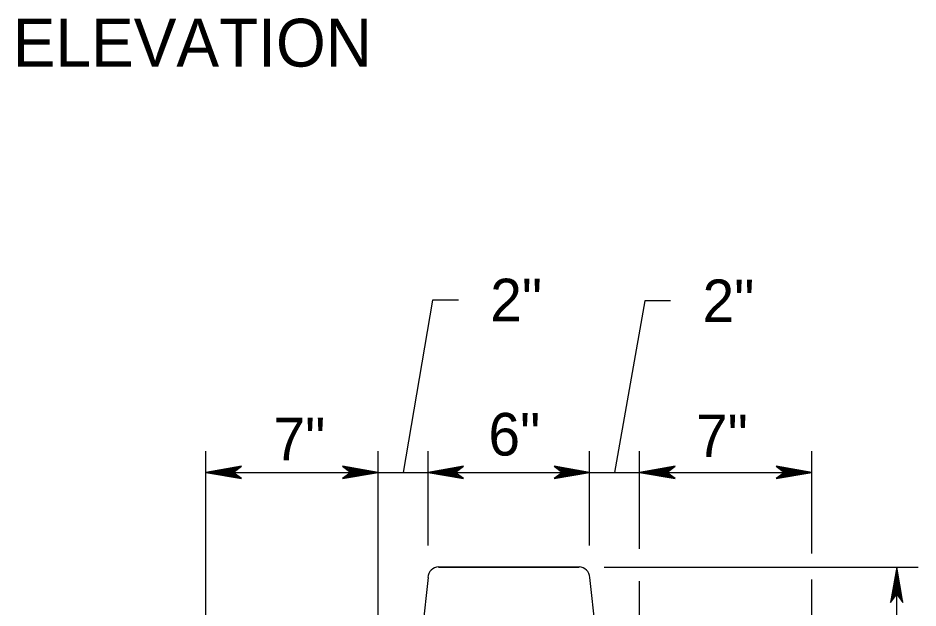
# Model space of a CAD drawing. Extents: x 499866 to 500993, y 499985 to 500645.
# Drawn here: x 500327.9 to 500412.5, y 500404.9 to 500460.3 of the extents above; entities that cross this region are included whole.
import ezdxf

# ---------------------------------------------------------------- set-up
doc = ezdxf.new("R2010")
doc.units = 0
doc.layers.add('24', color=7, linetype='Continuous')
doc.layers.add('5', color=7, linetype='Continuous')

msp = doc.modelspace()

# ---------------------------------------------------------------- linework, layer by layer
at = {"layer": '24'}
for points in [[(500345.582, 500417.598), (500348.932, 500417.006), (500348.132, 500417.598), (500348.915, 500418.181), (500345.582, 500417.598), (500345.804, 500417.604), (500348.838, 500417.05), (500348.069, 500417.605), (500348.78, 500418.135), (500345.925, 500417.614), (500346.036, 500417.598), (500348.635, 500417.136), (500348.052, 500417.605), (500348.651, 500418.059), (500346.087, 500417.597), (500346.198, 500417.614), (500348.47, 500417.204), (500348.028, 500417.597), (500348.479, 500418.006), (500346.522, 500417.615), (500346.711, 500417.614), (500348.302, 500417.289), (500347.992, 500417.588), (500348.325, 500417.921), (500346.745, 500417.598), (500346.924, 500417.587), (500348.119, 500417.383), (500347.889, 500417.615), (500348.139, 500417.844), (500347.088, 500417.598), (500347.257, 500417.581), (500347.975, 500417.444), (500347.857, 500417.605), (500348.052, 500417.784), (500347.344, 500417.597), (500347.813, 500417.486), (500347.745, 500417.614), (500347.95, 500417.743), (500347.462, 500417.615), (500347.769, 500417.538), (500347.64, 500417.639), (500347.788, 500417.699), (500347.641, 500417.605), (500347.718, 500417.588)], [(500361.763, 500417.598), (500358.413, 500418.19), (500359.214, 500417.598), (500358.43, 500417.015), (500361.763, 500417.598), (500361.541, 500417.592), (500358.507, 500418.146), (500359.276, 500417.591), (500358.566, 500417.061), (500361.421, 500417.581), (500361.309, 500417.598), (500358.71, 500418.06), (500359.293, 500417.591), (500358.694, 500417.136), (500361.258, 500417.598), (500361.147, 500417.581), (500358.875, 500417.991), (500359.317, 500417.598), (500358.866, 500417.189), (500360.823, 500417.581), (500360.634, 500417.581), (500359.044, 500417.907), (500359.353, 500417.607), (500359.02, 500417.274), (500360.6, 500417.598), (500360.422, 500417.608), (500359.226, 500417.813), (500359.456, 500417.581), (500359.206, 500417.352), (500360.257, 500417.598), (500360.089, 500417.615), (500359.37, 500417.752), (500359.489, 500417.591), (500359.293, 500417.412), (500360.001, 500417.598), (500359.532, 500417.709), (500359.6, 500417.581), (500359.395, 500417.453), (500359.883, 500417.581), (500359.576, 500417.658), (500359.705, 500417.557), (500359.557, 500417.496), (500359.704, 500417.591), (500359.627, 500417.607)], [(500366.46, 500417.598), (500369.81, 500417.006), (500369.01, 500417.598), (500369.793, 500418.181), (500366.46, 500417.598), (500366.683, 500417.604), (500369.717, 500417.05), (500368.948, 500417.605), (500369.658, 500418.135), (500366.803, 500417.614), (500366.914, 500417.598), (500369.513, 500417.136), (500368.93, 500417.605), (500369.53, 500418.059), (500366.966, 500417.597), (500367.077, 500417.614), (500369.348, 500417.204), (500368.906, 500417.597), (500369.358, 500418.006), (500367.4, 500417.615), (500367.589, 500417.614), (500369.18, 500417.289), (500368.87, 500417.588), (500369.204, 500417.921), (500367.623, 500417.598), (500367.802, 500417.587), (500368.998, 500417.383), (500368.768, 500417.615), (500369.017, 500417.844), (500367.966, 500417.598), (500368.135, 500417.581), (500368.853, 500417.444), (500368.735, 500417.605), (500368.93, 500417.784), (500368.222, 500417.597), (500368.691, 500417.486), (500368.623, 500417.614), (500368.829, 500417.743), (500368.34, 500417.615), (500368.648, 500417.538), (500368.519, 500417.639), (500368.667, 500417.699), (500368.52, 500417.605), (500368.596, 500417.588)], [(500381.66, 500417.598), (500378.31, 500418.19), (500379.111, 500417.598), (500378.328, 500417.015), (500381.66, 500417.598), (500381.438, 500417.592), (500378.404, 500418.146), (500379.173, 500417.591), (500378.463, 500417.061), (500381.318, 500417.581), (500381.206, 500417.598), (500378.608, 500418.06), (500379.191, 500417.591), (500378.591, 500417.136), (500381.155, 500417.598), (500381.044, 500417.581), (500378.772, 500417.991), (500379.214, 500417.598), (500378.763, 500417.189), (500380.72, 500417.581), (500380.531, 500417.581), (500378.941, 500417.907), (500379.25, 500417.607), (500378.917, 500417.274), (500380.498, 500417.598), (500380.319, 500417.608), (500379.123, 500417.813), (500379.353, 500417.581), (500379.104, 500417.352), (500380.155, 500417.598), (500379.986, 500417.615), (500379.267, 500417.752), (500379.386, 500417.591), (500379.19, 500417.412), (500379.898, 500417.598), (500379.43, 500417.709), (500379.498, 500417.581), (500379.292, 500417.453), (500379.781, 500417.581), (500379.473, 500417.658), (500379.602, 500417.557), (500379.454, 500417.496), (500379.601, 500417.591), (500379.524, 500417.607)], [(500386.357, 500417.598), (500389.707, 500417.006), (500388.907, 500417.598), (500389.69, 500418.181), (500386.357, 500417.598), (500386.58, 500417.604), (500389.614, 500417.05), (500388.844, 500417.605), (500389.555, 500418.135), (500386.7, 500417.614), (500386.811, 500417.598), (500389.41, 500417.136), (500388.827, 500417.605), (500389.427, 500418.059), (500386.863, 500417.597), (500386.974, 500417.614), (500389.245, 500417.204), (500388.803, 500417.597), (500389.255, 500418.006), (500387.297, 500417.615), (500387.486, 500417.614), (500389.077, 500417.289), (500388.767, 500417.588), (500389.101, 500417.921), (500387.52, 500417.598), (500387.699, 500417.587), (500388.895, 500417.383), (500388.665, 500417.615), (500388.914, 500417.844), (500387.863, 500417.598), (500388.032, 500417.581), (500388.75, 500417.444), (500388.632, 500417.605), (500388.827, 500417.784), (500388.119, 500417.597), (500388.588, 500417.486), (500388.52, 500417.614), (500388.726, 500417.743), (500388.237, 500417.615), (500388.545, 500417.538), (500388.416, 500417.639), (500388.564, 500417.699), (500388.417, 500417.605), (500388.493, 500417.588)], [(500402.539, 500417.598), (500399.189, 500418.19), (500399.989, 500417.598), (500399.206, 500417.015), (500402.539, 500417.598), (500402.316, 500417.592), (500399.282, 500418.146), (500400.052, 500417.591), (500399.341, 500417.061), (500402.196, 500417.581), (500402.085, 500417.598), (500399.486, 500418.06), (500400.069, 500417.591), (500399.469, 500417.136), (500402.033, 500417.598), (500401.922, 500417.581), (500399.651, 500417.991), (500400.093, 500417.598), (500399.641, 500417.189), (500401.599, 500417.581), (500401.41, 500417.581), (500399.819, 500417.907), (500400.129, 500417.607), (500399.795, 500417.274), (500401.376, 500417.598), (500401.197, 500417.608), (500400.001, 500417.813), (500400.231, 500417.581), (500399.982, 500417.352), (500401.033, 500417.598), (500400.864, 500417.615), (500400.146, 500417.752), (500400.264, 500417.591), (500400.069, 500417.412), (500400.777, 500417.598), (500400.308, 500417.709), (500400.376, 500417.581), (500400.17, 500417.453), (500400.659, 500417.581), (500400.351, 500417.658), (500400.48, 500417.557), (500400.332, 500417.496), (500400.479, 500417.591), (500400.403, 500417.607)], [(500410.532, 500408.703), (500409.94, 500405.353), (500410.532, 500406.153), (500411.115, 500405.37), (500410.532, 500408.703), (500410.538, 500408.48), (500409.984, 500405.447), (500410.54, 500406.216), (500411.07, 500405.505), (500410.549, 500408.36), (500410.532, 500408.249), (500410.071, 500405.65), (500410.539, 500406.233), (500410.994, 500405.634), (500410.532, 500408.198), (500410.549, 500408.086), (500410.139, 500405.815), (500410.532, 500406.257), (500410.941, 500405.805), (500410.55, 500407.763), (500410.549, 500407.574), (500410.223, 500405.983), (500410.523, 500406.293), (500410.856, 500405.959), (500410.532, 500407.54), (500410.522, 500407.361), (500410.317, 500406.165), (500410.55, 500406.395), (500410.779, 500406.146), (500410.532, 500407.197), (500410.515, 500407.028), (500410.378, 500406.31), (500410.54, 500406.428), (500410.719, 500406.233), (500410.532, 500406.941), (500410.421, 500406.472), (500410.549, 500406.54), (500410.677, 500406.334), (500410.55, 500406.823), (500410.472, 500406.515), (500410.573, 500406.644), (500410.634, 500406.496), (500410.54, 500406.643), (500410.523, 500406.567)]]:
    msp.add_lwpolyline(points, dxfattribs=at)
at = {"layer": '5'}
for p, q in [((500345.582, 500400.472), (500345.582, 500419.596)), ((500361.763, 500388.463), (500361.763, 500419.596)), ((500366.46, 500410.728), (500366.46, 500419.596)), ((500381.66, 500410.728), (500381.66, 500419.596)), ((500386.357, 500410.423), (500386.357, 500419.596)), ((500402.539, 500409.964), (500402.539, 500419.596)), ((500345.582, 500417.598), (500361.763, 500417.598)), ((500361.763, 500417.598), (500366.46, 500417.598)), ((500366.46, 500417.598), (500381.66, 500417.598)), ((500381.66, 500417.598), (500386.357, 500417.598)), ((500386.357, 500417.598), (500402.539, 500417.598)), ((500367.458, 500408.703), (500380.662, 500408.703)), ((500380.662, 500408.703), (500367.458, 500408.703)), ((500383.021, 500408.703), (500412.531, 500408.703)), ((500410.532, 500360.436), (500410.532, 500408.703)), ((500366.46, 500407.71), (500361.763, 500363.268)), ((500381.66, 500407.71), (500386.357, 500363.268)), ((500386.357, 500370.823), (500386.357, 500407.365)), ((500402.539, 500361.649), (500402.539, 500407.518))]:
    msp.add_line(p, q, dxfattribs=at)
for points in [[(500369.312, 500433.791), (500366.893, 500433.791), (500364.112, 500417.598)], [(500389.273, 500433.715), (500386.853, 500433.715), (500384.009, 500417.598)]]:
    msp.add_lwpolyline(points, dxfattribs=at)
for centre, start, end in [((500367.458, 500407.71), 90, 180), ((500380.662, 500407.71), 0, 90)]:
    msp.add_arc(centre, 0.999, start, end, dxfattribs=at)

# ---------------------------------------------------------------- texts
for s, height, p in [('ELEVATION', 4.5, (500327.417, 500455.721)), ('2"', 4, (500372.312, 500431.791)), ('2"', 4, (500392.273, 500431.715)), ('6"', 4, (500372.141, 500419.176)), ('7"', 4, (500391.66, 500419.03)), ('7"', 4, (500351.933, 500418.726))]:
    msp.add_text(s, height=height, dxfattribs=at).set_placement(p)

doc.saveas('drawing.dxf')
